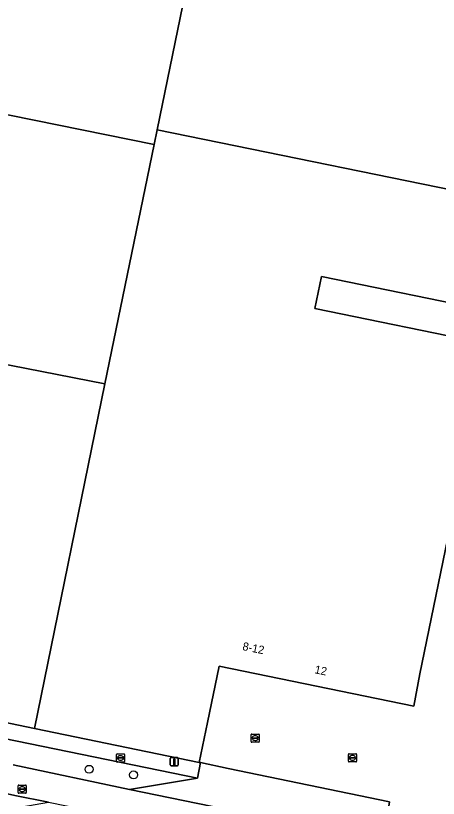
# Model space of a CAD drawing. Extents: x 157692 to 159674, y 381452 to 383291.
# Drawn here: x 158606.9 to 158658.8, y 382113.2 to 382209.3 of the extents above; entities that cross this region are included whole.
import ezdxf

# ---------------------------------------------------------------- set-up
doc = ezdxf.new("R2010")
doc.units = 0
for name, color, linetype in [('IMGEO_Berm_groen', 7, 'Continuous'), ('IMGEO_Boom', 7, 'Continuous'), ('IMGEO_Brandkraan', 7, 'Continuous'), ('IMGEO_Erf', 7, 'Continuous'), ('IMGEO_Fietspad_gesloten', 7, 'Continuous'), ('IMGEO_Kolk', 7, 'Continuous'), ('IMGEO_Lichtmast', 7, 'Continuous'), ('IMGEO_Pand', 7, 'Continuous'), ('IMGEO_Pand_nummerreeks', 7, 'Continuous'), ('IMGEO_Rijbaan_lokaal_open', 7, 'Continuous'), ('IMGEO_Rioolput', 7, 'Continuous'), ('IMGEO_Voetpad_open', 7, 'Continuous')]:
    doc.layers.add(name, color=color, linetype=linetype)

msp = doc.modelspace()

# ---------------------------------------------------------------- linework, layer by layer
at = {"layer": 'IMGEO_Berm_groen'}
for points in [[(158606.65, 382117.341), (158620.94, 382114.323), (158629.259, 382115.706), (158553.236, 382131.308)], [(158591.784, 382115.861), (158602.963, 382112.362), (158605.115, 382111.751), (158610.985, 382112.743), (158606.841, 382113.579), (158601.914, 382114.691), (158593.588, 382117.233), (158589.111, 382118.343)]]:
    msp.add_lwpolyline(points, dxfattribs=at)
at = {"layer": 'IMGEO_Boom'}
for centre in [(158615.968, 382116.792), (158621.416, 382116.113)]:
    msp.add_circle(centre, 0.489, dxfattribs=at)
at = {"layer": 'IMGEO_Brandkraan'}
for p, q in [((158619.323, 382117.759), (158619.323, 382118.611)), ((158619.398, 382118.685), (158620.25, 382118.685)), ((158619.582, 382118.179), (158619.582, 382118.191)), ((158620.02, 382118.142), (158619.622, 382118.142)), ((158619.625, 382118.228), (158620.023, 382118.228)), ((158619.834, 382117.905), (158619.809, 382117.905)), ((158619.811, 382118.465), (158619.836, 382118.465)), ((158620.066, 382118.191), (158620.066, 382118.179)), ((158620.324, 382118.611), (158620.324, 382117.759)), ((158620.25, 382117.685), (158619.398, 382117.685))]:
    msp.add_line(p, q, dxfattribs=at)
for points in [[(158619.323, 382117.759), (158619.323, 382118.611)], [(158619.398, 382118.685), (158620.25, 382118.685)], [(158620.324, 382118.611), (158620.324, 382117.759)], [(158620.25, 382117.685), (158619.398, 382117.685)]]:
    msp.add_lwpolyline(points, dxfattribs=at)
for centre, radius, start, end in [((158619.4, 382118.609), 0.0765, 91.55205, 178.44795), ((158619.4, 382118.609), 0.0765, 91.55205, 178.44795), ((158619.622, 382118.188), 0.0403, 85.87752, 175.75265), ((158619.619, 382118.178), 0.0366, 178.93798, 274.71019), ((158620.023, 382118.185), 0.043, 264.86636, 352.45326), ((158620.027, 382118.19), 0.0386, 1.73085, 96.63898), ((158620.248, 382118.609), 0.0765, 1.55205, 88.44795), ((158620.248, 382118.609), 0.0765, 1.55205, 88.44795), ((158619.4, 382117.761), 0.0765, 181.55205, 268.44795), ((158619.4, 382117.761), 0.0765, 181.55205, 268.44795), ((158620.248, 382117.761), 0.0765, 271.55205, 358.44795), ((158620.248, 382117.761), 0.0765, 271.55205, 358.44795)]:
    msp.add_arc(centre, radius, start, end, dxfattribs=at)
for centre, major_axis, ratio, start_param, end_param in [((158619.81, 382118.185), (-0.387, 0.002), 0.722429, 4.712389, 7.853982), ((158619.835, 382118.185), (-0.39, 0.002), 0.717154, 1.570796, 4.712389)]:
    msp.add_ellipse(centre, major_axis=major_axis, ratio=ratio, start_param=start_param, end_param=end_param, dxfattribs=at)
at = {"layer": 'IMGEO_Erf'}
msp.add_lwpolyline([(158629.34, 382219.832), (158624.324, 382195.285), (158668.371, 382186.284), (158669.37, 382191.168), (158671.809, 382190.668), (158680.461, 382232.951)], dxfattribs=at)
msp.add_lwpolyline([(158675.794, 382141.737), (158661.23, 382144.746), (158659.934, 382145.014), (158656.565, 382128.528), (158655.827, 382124.558), (158631.911, 382129.446), (158630.497, 382122.547), (158629.493, 382117.649), (158629.645, 382117.616), (158633.042, 382116.888), (158652.814, 382112.789), (158652.528, 382111.031), (158663.137, 382108.85), (158663.538, 382110.748), (158665.906, 382122.186), (158671.563, 382121.096)], close=True, dxfattribs=at)
at = {"layer": 'IMGEO_Fietspad_gesloten'}
for points in [[(158551.776, 382125.053), (158552.592, 382124.924), (158589.111, 382118.343), (158593.588, 382117.233), (158601.914, 382114.691), (158606.841, 382113.579), (158610.985, 382112.743), (158640.458, 382106.746), (158759.226, 382082.344), (158791.317, 382075.663), (158799.46, 382073.968), (158814.721, 382069.044), (158815.071, 382068.931), (158816.815, 382072.002), (158813.002, 382074.196)], [(158620.94, 382114.323), (158606.65, 382117.341)], [(158809.708, 382075.476), (158712.956, 382095.452), (158620.94, 382114.323)]]:
    msp.add_lwpolyline(points, dxfattribs=at)
at = {"layer": 'IMGEO_Kolk'}
for p, q in [((158635.849, 382120.194), (158635.849, 382121.046)), ((158635.924, 382121.12), (158636.776, 382121.12)), ((158636.337, 382120.9), (158636.362, 382120.9)), ((158636.85, 382121.046), (158636.85, 382120.194)), ((158636.776, 382120.12), (158635.924, 382120.12)), ((158636.108, 382120.614), (158636.108, 382120.626)), ((158636.546, 382120.577), (158636.148, 382120.577)), ((158636.151, 382120.663), (158636.549, 382120.663)), ((158636.36, 382120.34), (158636.335, 382120.34)), ((158636.592, 382120.626), (158636.592, 382120.614)), ((158647.789, 382117.778), (158647.789, 382118.63)), ((158647.864, 382118.704), (158648.716, 382118.704)), ((158648.048, 382118.198), (158648.048, 382118.21)), ((158648.486, 382118.161), (158648.088, 382118.161)), ((158648.091, 382118.247), (158648.489, 382118.247)), ((158648.3, 382117.924), (158648.275, 382117.924)), ((158648.277, 382118.484), (158648.302, 382118.484)), ((158648.532, 382118.21), (158648.532, 382118.198)), ((158648.79, 382118.63), (158648.79, 382117.778)), ((158648.716, 382117.704), (158647.864, 382117.704))]:
    msp.add_line(p, q, dxfattribs=at)
for points in [[(158635.849, 382120.194), (158635.849, 382121.046)], [(158635.924, 382121.12), (158636.776, 382121.12)], [(158636.85, 382121.046), (158636.85, 382120.194)], [(158636.776, 382120.12), (158635.924, 382120.12)], [(158647.789, 382117.778), (158647.789, 382118.63)], [(158647.864, 382118.704), (158648.716, 382118.704)], [(158648.79, 382118.63), (158648.79, 382117.778)], [(158648.716, 382117.704), (158647.864, 382117.704)]]:
    msp.add_lwpolyline(points, dxfattribs=at)
for centre, radius, start, end in [((158635.926, 382121.044), 0.0765, 91.55205, 178.44795), ((158635.926, 382121.044), 0.0765, 91.55205, 178.44795), ((158636.774, 382121.044), 0.0765, 1.55205, 88.44795), ((158636.774, 382121.044), 0.0765, 1.55205, 88.44795), ((158635.926, 382120.196), 0.0765, 181.55205, 268.44795), ((158635.926, 382120.196), 0.0765, 181.55205, 268.44795), ((158636.148, 382120.623), 0.0403, 85.87752, 175.75265), ((158636.145, 382120.613), 0.0366, 178.93798, 274.71019), ((158636.549, 382120.62), 0.043, 264.86636, 352.45326), ((158636.553, 382120.625), 0.0386, 1.73085, 96.63898), ((158636.774, 382120.196), 0.0765, 271.55205, 358.44795), ((158636.774, 382120.196), 0.0765, 271.55205, 358.44795), ((158647.866, 382118.628), 0.0765, 91.55205, 178.44795), ((158647.866, 382118.628), 0.0765, 91.55205, 178.44795), ((158648.088, 382118.207), 0.0403, 85.87752, 175.75265), ((158648.085, 382118.197), 0.0366, 178.93798, 274.71019), ((158648.489, 382118.204), 0.043, 264.86636, 352.45326), ((158648.493, 382118.209), 0.0386, 1.73085, 96.63898), ((158648.714, 382118.628), 0.0765, 1.55205, 88.44795), ((158648.714, 382118.628), 0.0765, 1.55205, 88.44795), ((158647.866, 382117.78), 0.0765, 181.55205, 268.44795), ((158647.866, 382117.78), 0.0765, 181.55205, 268.44795), ((158648.714, 382117.78), 0.0765, 271.55205, 358.44795), ((158648.714, 382117.78), 0.0765, 271.55205, 358.44795)]:
    msp.add_arc(centre, radius, start, end, dxfattribs=at)
for centre, major_axis, ratio, start_param, end_param in [((158636.336, 382120.62), (-0.387, 0.002), 0.722429, 4.712389, 7.853982), ((158636.361, 382120.62), (-0.39, 0.002), 0.717154, 1.570796, 4.712389), ((158648.276, 382118.204), (-0.387, 0.002), 0.722429, 4.712389, 7.853982), ((158648.301, 382118.204), (-0.39, 0.002), 0.717154, 1.570796, 4.712389)]:
    msp.add_ellipse(centre, major_axis=major_axis, ratio=ratio, start_param=start_param, end_param=end_param, dxfattribs=at)
at = {"layer": 'IMGEO_Lichtmast'}
for p, q in [((158625.926, 382117.323), (158625.926, 382118.123)), ((158625.926, 382118.123), (158625.926, 382117.323)), ((158626.026, 382118.223), (158626.816, 382118.223)), ((158626.816, 382118.223), (158626.026, 382118.223)), ((158626.916, 382118.123), (158626.916, 382117.323)), ((158626.916, 382117.323), (158626.916, 382118.123)), ((158626.816, 382117.223), (158626.026, 382117.223)), ((158626.026, 382117.223), (158626.816, 382117.223))]:
    msp.add_line(p, q, dxfattribs=at)
msp.add_lwpolyline([(158626.346, 382118.098), (158626.496, 382118.098), (158626.496, 382117.348), (158626.346, 382117.348), (158626.346, 382118.098)], dxfattribs=at)
for centre, start, end in [((158626.026, 382118.123), 90, 180), ((158626.026, 382118.123), 90, 180), ((158626.816, 382118.123), 0, 90), ((158626.816, 382118.123), 360, 90), ((158626.026, 382117.323), 180, 270), ((158626.026, 382117.323), 180, 270), ((158626.816, 382117.323), 270, 0), ((158626.816, 382117.323), 270, 0)]:
    msp.add_arc(centre, 0.1, start, end, dxfattribs=at)
at = {"layer": 'IMGEO_Pand'}
for points in [[(158576.115, 382230.619), (158575.584, 382228.145), (158575.263, 382228.214), (158574.032, 382222.478), (158571.367, 382223.019), (158571.578, 382224.05), (158562.884, 382225.827), (158561.639, 382219.733), (158563.119, 382219.432), (158562.364, 382215.729), (158560.882, 382216.032), (158558.961, 382206.635), (158623.952, 382193.477), (158624.324, 382195.285), (158629.34, 382219.832), (158581.016, 382229.628)], [(158623.952, 382193.477), (158558.961, 382206.635), (158556.948, 382196.783), (158565.247, 382195.087), (158561.216, 382175.361), (158577.294, 382172.047), (158617.909, 382164.108)], [(158664.838, 382169.014), (158643.683, 382173.337), (158644.484, 382177.257), (158665.62, 382172.937), (158665.79, 382173.771), (158668.371, 382186.284), (158624.324, 382195.285), (158623.952, 382193.477), (158617.909, 382164.108), (158609.261, 382121.797), (158629.493, 382117.649), (158630.497, 382122.547), (158631.911, 382129.446), (158655.827, 382124.558), (158656.565, 382128.528), (158659.934, 382145.014)], [(158702.925, 382184.289), (158671.809, 382190.668), (158669.37, 382191.168), (158668.371, 382186.284), (158665.79, 382173.771), (158665.62, 382172.937), (158644.484, 382177.257), (158643.683, 382173.337), (158664.838, 382169.014), (158659.934, 382145.014), (158661.23, 382144.746), (158675.794, 382141.737), (158671.563, 382121.096), (158669.221, 382109.671), (158669.5, 382109.614), (158686.958, 382106.032)], [(158617.909, 382164.108), (158577.294, 382172.047), (158575.023, 382161.028), (158564.131, 382163.272), (158558.548, 382136.172), (158557.225, 382136.428), (158556.568, 382133.298), (158554.818, 382133.659), (158554.772, 382133.456), (158563.315, 382131.7), (158563.223, 382131.236), (158573.743, 382129.079), (158604.33, 382122.808), (158609.261, 382121.797)]]:
    msp.add_lwpolyline(points, close=True, dxfattribs=at)
at = {"layer": 'IMGEO_Rijbaan_lokaal_open'}
msp.add_lwpolyline([(158665.285, 382106.51), (158663.872, 382108.691), (158663.137, 382108.85), (158652.528, 382111.031), (158652.814, 382112.789), (158633.042, 382116.888), (158629.645, 382117.616), (158629.259, 382115.706), (158620.94, 382114.323), (158712.956, 382095.452), (158809.708, 382075.476)], dxfattribs=at)
at = {"layer": 'IMGEO_Rioolput'}
for p, q in [((158607.249, 382113.928), (158607.249, 382114.78)), ((158607.324, 382114.854), (158608.176, 382114.854)), ((158607.508, 382114.348), (158607.508, 382114.36)), ((158607.946, 382114.311), (158607.548, 382114.311)), ((158607.551, 382114.397), (158607.949, 382114.397)), ((158607.76, 382114.074), (158607.735, 382114.074)), ((158607.737, 382114.634), (158607.762, 382114.634)), ((158607.992, 382114.36), (158607.992, 382114.348)), ((158608.25, 382114.78), (158608.25, 382113.928)), ((158608.176, 382113.854), (158607.324, 382113.854))]:
    msp.add_line(p, q, dxfattribs=at)
for points in [[(158607.249, 382113.928), (158607.249, 382114.78)], [(158607.324, 382114.854), (158608.176, 382114.854)], [(158608.25, 382114.78), (158608.25, 382113.928)], [(158608.176, 382113.854), (158607.324, 382113.854)]]:
    msp.add_lwpolyline(points, dxfattribs=at)
for centre, radius, start, end in [((158607.326, 382114.778), 0.0765, 91.55205, 178.44795), ((158607.326, 382114.778), 0.0765, 91.55205, 178.44795), ((158607.548, 382114.357), 0.0403, 85.87752, 175.75265), ((158607.545, 382114.347), 0.0366, 178.93798, 274.71019), ((158607.949, 382114.354), 0.043, 264.86636, 352.45326), ((158607.953, 382114.359), 0.0386, 1.73085, 96.63898), ((158608.174, 382114.778), 0.0765, 1.55205, 88.44795), ((158608.174, 382114.778), 0.0765, 1.55205, 88.44795), ((158607.326, 382113.93), 0.0765, 181.55205, 268.44795), ((158607.326, 382113.93), 0.0765, 181.55205, 268.44795), ((158608.174, 382113.93), 0.0765, 271.55205, 358.44795), ((158608.174, 382113.93), 0.0765, 271.55205, 358.44795)]:
    msp.add_arc(centre, radius, start, end, dxfattribs=at)
for centre, major_axis, ratio, start_param, end_param in [((158607.736, 382114.354), (-0.387, 0.002), 0.722429, 4.712389, 7.853982), ((158607.761, 382114.354), (-0.39, 0.002), 0.717154, 1.570796, 4.712389)]:
    msp.add_ellipse(centre, major_axis=major_axis, ratio=ratio, start_param=start_param, end_param=end_param, dxfattribs=at)
at = {"layer": 'IMGEO_Voetpad_open'}
msp.add_lwpolyline([(158539.73, 382130.783), (158540.362, 382133.945), (158550.307, 382131.839), (158549.746, 382129.001), (158552.692, 382128.489), (158553.236, 382131.308), (158629.259, 382115.706), (158629.645, 382117.616), (158629.493, 382117.649), (158609.261, 382121.797), (158604.33, 382122.808)], dxfattribs=at)

# ---------------------------------------------------------------- texts
at = {"layer": 'IMGEO_Pand_nummerreeks'}
for s, rotation, p in [('8-12', 348.44886, (158634.726, 382131.443)), ('12', 348.44917, (158643.58, 382128.592))]:
    msp.add_text(s, height=1, rotation=rotation, dxfattribs=at).set_placement(p)

doc.saveas('drawing.dxf')
